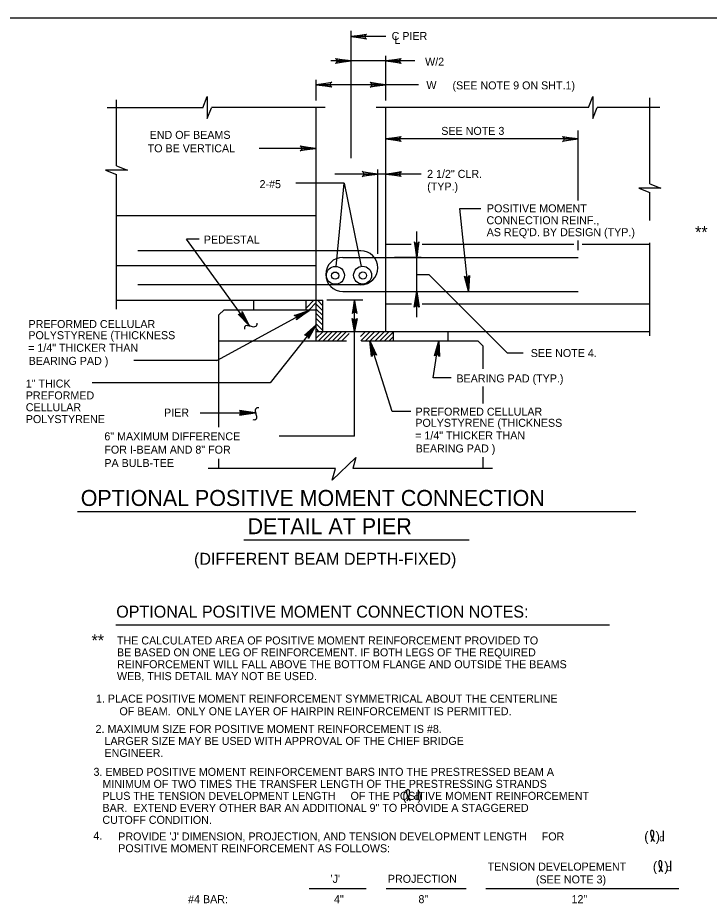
# Model space of a CAD drawing. Extents: x 639980 to 641204, y 298038 to 300414.
# Drawn here: x 640536.4 to 640795.5, y 298284.8 to 298616.8 of the extents above; entities that cross this region are included whole.
import ezdxf

# ---------------------------------------------------------------- set-up
doc = ezdxf.new("R2010")
doc.units = 0
for name, color, linetype in [('1', 7, 'Continuous'), ('2', 7, 'Continuous'), ('3', 7, 'Continuous')]:
    doc.layers.add(name, color=color, linetype=linetype)

msp = doc.modelspace()

# ---------------------------------------------------------------- linework, layer by layer
at = {"layer": '1'}
for p, q in [((640661.25, 298564.12), (640661.25, 298611.8)), ((640648.23, 298495.65), (640648.23, 298583.06)), ((640674.27, 298499.17), (640674.27, 298583.06)), ((640655.64, 298523.56), (640658.65, 298554.73)), ((640644.39, 298507.32), (640644.39, 298510.84)), ((640677.19, 298495.65), (640677.19, 298499.17)), ((640654.23, 298443.37), (640663.07, 298451.9)), ((640663.07, 298451.9), (640661.91, 298447.85)), ((640654.23, 298443.37), (640655.42, 298447.85))]:
    msp.add_line(p, q, dxfattribs=at)
for points in [[(640625.91, 298502.24), (640625.85, 298501.43), (640625.43, 298501), (640624.67, 298500.82), (640623.95, 298501.04), (640623.19, 298501.19), (640622.43, 298501.32), (640621.67, 298501.24), (640621.34, 298500.67), (640621.34, 298500.06)], [(640626.75, 298470.55), (640625.94, 298470.48), (640625.51, 298470.07), (640625.34, 298469.31), (640625.55, 298468.59), (640625.71, 298467.83), (640625.84, 298467.06), (640625.75, 298466.3), (640625.18, 298465.98), (640624.58, 298465.98)]]:
    msp.add_spline(points, degree=3, dxfattribs=at)
at = {"layer": '2'}
for p, q in [((640020.31, 298616.78), (640806.31, 298616.78)), ((640674.27, 298609.72), (640661.25, 298609.72)), ((640674.27, 298585.75), (640674.27, 298602.54)), ((640661.25, 298600.56), (640653.65, 298600.56)), ((640674.27, 298600.56), (640661.25, 298600.56)), ((640685.17, 298600.56), (640674.27, 298600.56)), ((640648.23, 298585.75), (640648.23, 298593.54)), ((640674.27, 298591.66), (640648.23, 298591.66)), ((640686.59, 298591.66), (640674.27, 298591.66)), ((640573.35, 298561.2), (640573.35, 298586)), ((640605.78, 298583), (640607.41, 298587.19)), ((640607.41, 298587.19), (640607.41, 298578.94)), ((640750.26, 298583.11), (640751.89, 298587.3)), ((640751.89, 298587.3), (640751.89, 298579.05)), ((640773.23, 298554.51), (640773.23, 298586.73)), ((640605.78, 298583), (640569.83, 298583)), ((640607.41, 298578.94), (640609, 298583)), ((640651.53, 298583.06), (640609, 298583.06)), ((640750.26, 298583.06), (640670.64, 298583.06)), ((640751.89, 298579.05), (640753.48, 298583.11)), ((640777.01, 298583.11), (640753.48, 298583.11)), ((640746.33, 298548.32), (640746.33, 298574.48)), ((640746.33, 298571.34), (640674.27, 298571.34)), ((640648.04, 298567.77), (640626.88, 298567.77)), ((640577.54, 298559.57), (640569.29, 298559.57)), ((640569.29, 298559.57), (640573.35, 298557.98)), ((640573.35, 298561.2), (640577.54, 298559.57)), ((640671.3, 298528.21), (640671.3, 298559.94)), ((640573.41, 298507.57), (640573.41, 298557.98)), ((640674.27, 298558.15), (640655.13, 298558.15)), ((640687.59, 298558.15), (640674.27, 298558.15)), ((640658.65, 298554.73), (640640.54, 298554.73)), ((640658.65, 298554.73), (640665.01, 298523.57)), ((640777.34, 298552.88), (640769.1, 298552.88)), ((640769.1, 298552.88), (640773.16, 298551.29)), ((640773.16, 298554.51), (640777.34, 298552.88)), ((640773.23, 298540.76), (640773.23, 298551.29)), ((640573.41, 298542.68), (640648.23, 298542.68)), ((640702, 298545.23), (640709.84, 298545.23)), ((640705.32, 298514.23), (640702, 298545.23)), ((640623.1, 298501.38), (640599.61, 298533.81)), ((640604.35, 298533.81), (640599.61, 298533.81)), ((640746.33, 298529.65), (640746.33, 298533.26)), ((640664.9, 298529.44), (640581.38, 298529.44)), ((640674.27, 298531.85), (640683.84, 298531.85)), ((640687.93, 298531.85), (640744.74, 298531.85)), ((640747.81, 298531.85), (640773.23, 298531.85)), ((640773.23, 298497.55), (640773.23, 298532.41)), ((640658.17, 298526.94), (640746.33, 298526.94)), ((640687.59, 298526.94), (640677.54, 298526.94)), ((640573.41, 298523.86), (640648.23, 298523.86)), ((640685.89, 298520.53), (640690.44, 298520.53)), ((640719.91, 298491.09), (640690.44, 298520.53)), ((640664.9, 298516.62), (640581.38, 298516.62)), ((640658.17, 298514.12), (640746.33, 298514.12)), ((640573.41, 298510.84), (640650.7, 298510.84)), ((640624.79, 298507.32), (640624.79, 298510.84)), ((640644.39, 298507.93), (640647.34, 298510.88)), ((640645.52, 298507.29), (640648.23, 298510)), ((640648.68, 298510.84), (640650.7, 298508.82)), ((640650.7, 298499.21), (640650.7, 298510.84)), ((640665.65, 298510.84), (640652.17, 298510.84)), ((640662.58, 298499.17), (640662.58, 298510.75)), ((640674.59, 298509.48), (640683.9, 298509.48)), ((640687.87, 298509.48), (640773.23, 298509.48)), ((640611.77, 298505.37), (640613.69, 298507.29)), ((640613.69, 298507.29), (640648.23, 298507.29)), ((640648.23, 298509.38), (640650.7, 298506.9)), ((640648.23, 298507.58), (640650.7, 298505.11)), ((640610.94, 298488.29), (640641.91, 298505.11)), ((640611.77, 298463.3), (640611.77, 298505.37)), ((640648.23, 298505.93), (640650.7, 298503.46)), ((640648.23, 298503.99), (640650.7, 298501.52)), ((640648.23, 298501.71), (640630.91, 298479.97)), ((640648.23, 298502.04), (640650.7, 298499.57)), ((640648.23, 298500.1), (640649.12, 298499.21)), ((640648.23, 298499.17), (640773.23, 298499.17)), ((640648.23, 298496.62), (640650.78, 298499.17)), ((640649.03, 298495.65), (640652.55, 298499.17)), ((640650.79, 298495.65), (640654.31, 298499.17)), ((640652.56, 298495.65), (640656.08, 298499.17)), ((640654.33, 298495.65), (640657.85, 298499.17)), ((640656.1, 298495.65), (640659.62, 298499.17)), ((640657.86, 298495.65), (640660.61, 298498.4)), ((640662.58, 298459.94), (640662.58, 298499.17)), ((640664.79, 298497.28), (640666.69, 298499.17)), ((640664.93, 298495.65), (640668.46, 298499.17)), ((640666.7, 298495.65), (640670.22, 298499.17)), ((640668.47, 298495.65), (640671.99, 298499.17)), ((640670.24, 298495.65), (640673.76, 298499.17)), ((640672.01, 298495.65), (640675.53, 298499.17)), ((640673.77, 298495.65), (640677.19, 298499.07)), ((640675.54, 298495.65), (640677.19, 298497.3)), ((640697.7, 298495.65), (640697.7, 298499.17)), ((640611.77, 298495.65), (640659.5, 298495.65)), ((640665.14, 298495.65), (640708.77, 298495.65)), ((640676.7, 298469.15), (640668.29, 298495.65)), ((640692.08, 298481.73), (640694.21, 298495.65)), ((640710.73, 298493.7), (640708.77, 298495.65)), ((640710.73, 298485.19), (640710.73, 298493.7)), ((640725.77, 298491.09), (640719.91, 298491.09)), ((640610.94, 298488.29), (640579.86, 298488.29)), ((640630.91, 298479.97), (640564.33, 298479.97)), ((640698.83, 298481.73), (640692.08, 298481.73)), ((640710.73, 298472.16), (640710.73, 298478.51)), ((640604.75, 298468.67), (640625.3, 298468.67)), ((640683.71, 298469.15), (640676.7, 298469.15)), ((640662.58, 298459.94), (640634.35, 298459.94)), ((640611.77, 298447.85), (640611.77, 298451.48)), ((640710.73, 298447.85), (640710.73, 298452.01)), ((640655.42, 298447.85), (640607.71, 298447.85)), ((640714.26, 298447.85), (640661.91, 298447.85)), ((640558.77, 298431.71), (640767.95, 298431.71)), ((640621.05, 298421.12), (640705.53, 298421.12)), ((640573.13, 298389.22), (640758.14, 298389.22)), ((640682.78, 298327.39), (640682.78, 298327.39)), ((640683.19, 298326.87), (640683.11, 298327.07)), ((640686.57, 298323.52), (640686.57, 298327.35)), ((640682.06, 298326.82), (640682.07, 298326.26)), ((640682.08, 298326.15), (640682.24, 298325.45)), ((640682.16, 298323.25), (640682.49, 298323.64)), ((640682.27, 298325.36), (640682.51, 298324.78)), ((640682.54, 298324.72), (640682.92, 298324.03)), ((640682.56, 298323.74), (640682.76, 298324.1)), ((640682.8, 298324.21), (640683.02, 298324.95)), ((640682.95, 298323.98), (640683.46, 298323.25)), ((640683.04, 298325), (640683.21, 298325.88)), ((640683.22, 298325.98), (640683.24, 298326.63)), ((640773.5, 298311.5), (640773.51, 298310.95)), ((640773.52, 298310.83), (640773.68, 298310.14)), ((640774.22, 298312.08), (640774.22, 298312.08)), ((640774.48, 298309.69), (640774.65, 298310.57)), ((640774.63, 298311.56), (640774.55, 298311.76)), ((640774.66, 298310.67), (640774.68, 298311.32)), ((640778.39, 298308.15), (640778.39, 298311.98)), ((640773.6, 298307.94), (640773.93, 298308.33)), ((640773.71, 298310.05), (640773.95, 298309.47)), ((640773.98, 298309.41), (640774.36, 298308.72)), ((640774, 298308.43), (640774.2, 298308.79)), ((640774.24, 298308.9), (640774.46, 298309.64)), ((640774.39, 298308.67), (640774.9, 298307.94)), ((640777.29, 298300.74), (640777.28, 298300.75)), ((640777.69, 298300.22), (640777.61, 298300.42)), ((640781.13, 298296.88), (640781.13, 298300.71)), ((640776.56, 298300.17), (640776.57, 298299.62)), ((640776.58, 298299.5), (640776.74, 298298.81)), ((640776.66, 298296.6), (640776.99, 298296.99)), ((640776.77, 298298.71), (640777.01, 298298.13)), ((640777.04, 298298.07), (640777.42, 298297.39)), ((640777.06, 298297.09), (640777.26, 298297.46)), ((640777.3, 298297.57), (640777.52, 298298.31)), ((640777.45, 298297.34), (640777.96, 298296.6)), ((640777.54, 298298.36), (640777.71, 298299.23)), ((640777.73, 298299.34), (640777.74, 298299.99)), ((640645.61, 298290.38), (640666.89, 298290.38)), ((640674.37, 298290.38), (640704.4, 298290.38)), ((640711.75, 298290.38), (640784.13, 298290.38))]:
    msp.add_line(p, q, dxfattribs=at)
for points in [[(640666.78, 298609.03), (640666.58, 298609.43), (640661.25, 298609.72), (640666.78, 298609.03), (640667.07, 298608.78), (640661.25, 298609.72), (640666.57, 298609.98), (640666.77, 298610.38), (640661.25, 298609.72), (640667.07, 298610.65), (640666.77, 298610.38)], [(640655.71, 298601.26), (640655.92, 298600.86), (640661.25, 298600.56), (640655.71, 298601.26), (640655.43, 298601.5), (640661.25, 298600.56), (640655.92, 298600.3), (640655.73, 298599.9), (640661.25, 298600.56), (640655.43, 298599.64), (640655.73, 298599.9)], [(640679.8, 298599.87), (640679.6, 298600.27), (640674.27, 298600.56), (640679.8, 298599.87), (640680.09, 298599.63), (640674.27, 298600.56), (640679.59, 298600.83), (640679.79, 298601.22), (640674.27, 298600.56), (640680.09, 298601.49), (640679.79, 298601.22)], [(640653.76, 298590.97), (640653.56, 298591.37), (640648.23, 298591.66), (640653.76, 298590.97), (640654.05, 298590.73), (640648.23, 298591.66), (640653.55, 298591.93), (640653.75, 298592.32), (640648.23, 298591.66), (640654.05, 298592.59), (640653.75, 298592.32)], [(640653.76, 298590.97), (640653.56, 298591.37), (640648.23, 298591.66), (640653.76, 298590.97), (640654.05, 298590.73), (640648.23, 298591.66), (640653.55, 298591.93), (640653.75, 298592.32), (640648.23, 298591.66), (640654.05, 298592.59), (640653.75, 298592.32)], [(640668.73, 298592.36), (640668.94, 298591.96), (640674.27, 298591.66), (640668.73, 298592.36), (640668.45, 298592.6), (640674.27, 298591.66), (640668.94, 298591.4), (640668.75, 298591), (640674.27, 298591.66), (640668.45, 298590.74), (640668.75, 298591)], [(640679.8, 298570.65), (640679.6, 298571.05), (640674.27, 298571.34), (640679.8, 298570.65), (640680.09, 298570.41), (640674.27, 298571.34), (640679.59, 298571.61), (640679.79, 298572), (640674.27, 298571.34), (640680.09, 298572.27), (640679.79, 298572)], [(640740.8, 298572.04), (640741, 298571.64), (640746.33, 298571.34), (640740.8, 298572.04), (640740.51, 298572.28), (640746.33, 298571.34), (640741.01, 298571.08), (640740.81, 298570.68), (640746.33, 298571.34), (640740.51, 298570.42), (640740.81, 298570.68)], [(640642.5, 298568.47), (640642.71, 298568.07), (640648.04, 298567.77), (640642.5, 298568.47), (640642.22, 298568.71), (640648.04, 298567.77), (640642.71, 298567.51), (640642.52, 298567.11), (640648.04, 298567.77), (640642.22, 298566.85), (640642.52, 298567.11)], [(640665.77, 298558.84), (640665.98, 298558.44), (640671.3, 298558.15), (640665.77, 298558.84), (640665.49, 298559.09), (640671.3, 298558.15), (640665.98, 298557.89), (640665.79, 298557.49), (640671.3, 298558.15), (640665.49, 298557.22), (640665.79, 298557.49)], [(640679.8, 298557.45), (640679.6, 298557.85), (640674.27, 298558.15), (640679.8, 298557.45), (640680.09, 298557.21), (640674.27, 298558.15), (640679.59, 298558.41), (640679.79, 298558.81), (640674.27, 298558.15), (640680.09, 298559.07), (640679.79, 298558.81)], [(640685.19, 298532.47), (640685.59, 298532.27), (640685.89, 298526.94), (640685.19, 298532.47), (640684.95, 298532.76), (640685.89, 298526.94), (640686.15, 298532.26), (640686.55, 298532.46), (640685.89, 298526.94), (640686.81, 298532.76), (640686.55, 298532.46)], [(640705.42, 298519.81), (640705.05, 298519.56), (640705.32, 298514.23), (640705.42, 298519.81), (640705.64, 298520.11), (640705.32, 298514.23), (640704.49, 298519.49), (640704.08, 298519.65), (640705.32, 298514.23), (640703.78, 298519.92), (640704.08, 298519.65)], [(640685.19, 298508.58), (640685.59, 298508.79), (640685.89, 298514.12), (640685.19, 298508.58), (640684.95, 298508.3), (640685.89, 298514.12), (640686.15, 298508.8), (640686.55, 298508.6), (640685.89, 298514.12), (640686.81, 298508.3), (640686.55, 298508.6)], [(640663.28, 298506.14), (640662.88, 298506.31), (640662.58, 298510.75), (640663.28, 298506.14), (640663.52, 298505.91), (640662.58, 298510.75), (640662.32, 298506.32), (640661.92, 298506.16), (640662.58, 298510.75), (640661.66, 298505.91), (640661.92, 298506.16)], [(640620.47, 298506.3), (640620.26, 298505.9), (640623.1, 298501.38), (640620.47, 298506.3), (640620.5, 298506.67), (640623.1, 298501.38), (640619.81, 298505.57), (640619.37, 298505.5), (640623.1, 298501.38), (640618.98, 298505.59), (640619.37, 298505.5)], [(640640.33, 298505.12), (640640.7, 298504.86), (640645.56, 298507.05), (640640.33, 298505.12), (640639.96, 298505.2), (640645.56, 298507.05), (640640.96, 298504.36), (640640.97, 298503.92), (640645.56, 298507.05), (640640.82, 298503.55), (640640.97, 298503.92)], [(640663.28, 298503.79), (640662.88, 298503.62), (640662.58, 298499.17), (640663.28, 298503.79), (640663.52, 298504.02), (640662.58, 298499.17), (640662.32, 298503.61), (640661.92, 298503.77), (640662.58, 298499.17), (640661.66, 298504.02), (640661.92, 298503.77)], [(640644.24, 298497.81), (640644.68, 298497.72), (640648.23, 298501.71), (640644.24, 298497.81), (640643.87, 298497.74), (640648.23, 298501.71), (640645.12, 298497.38), (640645.31, 298496.98), (640648.23, 298501.71), (640645.33, 298496.58), (640645.31, 298496.98)], [(640669.13, 298490.14), (640669.46, 298490.45), (640668.29, 298495.65), (640669.13, 298490.14), (640668.98, 298489.8), (640668.29, 298495.65), (640670, 298490.6), (640670.43, 298490.52), (640668.29, 298495.65), (640670.77, 298490.31), (640670.43, 298490.52)], [(640692.85, 298490.24), (640693.28, 298490.4), (640694.21, 298495.65), (640692.85, 298490.24), (640692.58, 298489.99), (640694.21, 298495.65), (640693.83, 298490.34), (640694.2, 298490.1), (640694.21, 298495.65), (640694.43, 298489.77), (640694.2, 298490.1)], [(640619.77, 298467.98), (640619.97, 298468.38), (640625.3, 298468.67), (640619.77, 298467.98), (640619.48, 298467.74), (640625.3, 298468.67), (640619.98, 298468.94), (640619.78, 298469.33), (640625.3, 298468.67), (640619.48, 298469.6), (640619.78, 298469.33)], [(640682.38, 298327.4), (640682.33, 298327.39), (640682.17, 298327.18)], [(640773.82, 298312.09), (640773.77, 298312.08), (640773.61, 298311.87)], [(640776.88, 298300.76), (640776.83, 298300.74), (640776.68, 298300.53)]]:
    msp.add_lwpolyline(points, dxfattribs=at)
for centre, radius in [((640655.39, 298520.21), 3.36), ((640665.6, 298520.26), 3.36), ((640655.3, 298520.09), 1.35), ((640665.71, 298520.14), 1.35)]:
    msp.add_circle(centre, radius, dxfattribs=at)
for centre, radius, start, end in [((640664.9, 298523.03), 6.41, 270, 90), ((640658.17, 298520.53), 6.41, 90, 270), ((640682.64, 298326.83), 0.583, 142.942, 181.1567), ((640682.56, 298326.85), 0.583, 68.3745, 108.4443), ((640682.57, 298326.85), 0.583, 22.4358, 68.3745), ((640682.65, 298326.64), 0.583, 358.8549, 22.4358), ((640682.65, 298326.27), 0.583, 181.1567, 192.772), ((640682.81, 298325.58), 0.583, 192.772, 202.4051), ((640682.05, 298324.02), 0.583, 319.6823, 331.4731), ((640683.05, 298325), 0.583, 202.4051, 209.0413), ((640682.24, 298324.38), 0.583, 331.4731, 343.3094), ((640683.43, 298324.32), 0.583, 209.0413, 214.8098), ((640682.46, 298325.12), 0.583, 343.3094, 348.6689), ((640682.64, 298326), 0.583, 348.6689, 358.8549), ((640774.08, 298311.52), 0.583, 142.942, 181.1567), ((640774.09, 298310.96), 0.583, 181.1567, 192.772), ((640774, 298311.54), 0.583, 68.3745, 108.4443), ((640774.01, 298311.53), 0.583, 22.4358, 68.3745), ((640774.09, 298311.33), 0.583, 358.8549, 22.4358), ((640774.08, 298310.68), 0.583, 348.6689, 358.8549), ((640774.25, 298310.27), 0.583, 192.772, 202.4051), ((640773.49, 298308.71), 0.583, 319.6823, 331.4731), ((640774.49, 298309.69), 0.583, 202.4051, 209.0413), ((640773.68, 298309.07), 0.583, 331.4731, 343.3094), ((640774.87, 298309), 0.583, 209.0413, 214.8098), ((640773.9, 298309.81), 0.583, 343.3094, 348.6689), ((640777.14, 298300.18), 0.583, 142.942, 181.1567), ((640777.06, 298300.2), 0.583, 68.3745, 108.4443), ((640777.07, 298300.2), 0.583, 22.4358, 68.3745), ((640777.15, 298299.63), 0.583, 181.1567, 192.772), ((640777.31, 298298.94), 0.583, 192.772, 202.4051), ((640776.55, 298297.37), 0.583, 319.6823, 331.4731), ((640777.55, 298298.35), 0.583, 202.4051, 209.0413), ((640776.74, 298297.73), 0.583, 331.4731, 343.3094), ((640777.93, 298297.67), 0.583, 209.0413, 214.8098), ((640776.97, 298298.47), 0.583, 343.3094, 348.6689), ((640777.15, 298300), 0.583, 358.8549, 22.4358), ((640777.14, 298299.35), 0.583, 348.6689, 358.8549)]:
    msp.add_arc(centre, radius, start, end, dxfattribs=at)
at = {"layer": '3'}
msp.add_line((640685.89, 298504.5), (640685.89, 298536.62), dxfattribs=at)

# ---------------------------------------------------------------- texts
at = {"layer": '1'}
for s, height, p in [("PROVIDE 'J' DIMENSION, PROJECTION, AND TENSION DEVELOPMENT LENGTH     FOR ", 2.9999, (640574.03, 298308.38)), ('POSITIVE MOMENT REINFORCEMENT AS FOLLOWS:', 2.9999, (640574.03, 298303.94)), ('TENSION DEVELOPEMENT', 2.9999, (640712.43, 298297.07)), ("'J'", 3, (640653.59, 298292.49)), ('PROJECTION', 3, (640675.06, 298292.49)), ('(SEE NOTE 3)', 2.9999, (640730.52, 298292.27)), ('     #4 BAR:', 2.9999, (640594.64, 298284.86)), ('4"', 3, (640654.87, 298284.86)), ('8"', 3, (640686.51, 298284.86)), ('12"', 3, (640743.87, 298284.86))]:
    msp.add_text(s, height=height, dxfattribs=at).set_placement(p)
at = {"layer": '2'}
for s, height, p in [('(SEE NOTE 9 ON SHT.1)', 3, (640699.27, 298589.91)), ('SEE NOTE 3', 3, (640695.07, 298572.85)), ('SEE NOTE 4.', 3, (640728.59, 298489.58)), ('OPTIONAL POSITIVE MOMENT CONNECTION', 6, (640559.99, 298433.76)), ('DETAIL AT PIER', 6, (640622.49, 298423.18)), ('(DIFFERENT BEAM DEPTH-FIXED)', 4.5, (640602.43, 298411.69)), ('OPTIONAL POSITIVE MOMENT CONNECTION NOTES:', 4.5, (640573.29, 298391.89)), ('THE CALCULATED AREA OF POSITIVE MOMENT REINFORCEMENT PROVIDED TO ', 3, (640573.56, 298381.84)), ('BE BASED ON ONE LEG OF REINFORCEMENT. IF BOTH LEGS OF THE REQUIRED', 3, (640573.56, 298377.38)), ('REINFORCEMENT WILL FALL ABOVE THE BOTTOM FLANGE AND OUTSIDE THE BEAMS', 3, (640573.56, 298372.93)), ('WEB, THIS DETAIL MAY NOT BE USED.', 3, (640573.56, 298368.47)), ('1. PLACE POSITIVE MOMENT REINFORCEMENT SYMMETRICAL ABOUT THE CENTERLINE', 3, (640565.68, 298360.04)), ('OF BEAM.  ONLY ONE LAYER OF HAIRPIN REINFORCEMENT IS PERMITTED.', 3, (640574.49, 298355.3)), ('2. MAXIMUM SIZE FOR POSITIVE MOMENT REINFORCEMENT IS #8.', 3, (640565.54, 298348.68)), ('   LARGER SIZE MAY BE USED WITH APPROVAL OF THE CHIEF BRIDGE', 3, (640565.54, 298344.18)), ('   ENGINEER.', 3, (640565.54, 298339.68)), ('3. EMBED POSITIVE MOMENT REINFORCEMENT BARS INTO THE PRESTRESSED BEAM A', 3, (640564.77, 298332.59)), ('   MINIMUM OF TWO TIMES THE TRANSFER LENGTH OF THE PRESTRESSING STRANDS', 3, (640564.77, 298328.09)), ('(   )', 3.6, (640680.51, 298323.45)), ('   PLUS THE TENSION DEVELOPMENT LENGTH     OF THE POSITIVE MOMENT REINFORCEMENT', 3, (640564.77, 298323.59)), ('d', 2.5, (640684.91, 298323.52)), ('   BAR.  EXTEND EVERY OTHER BAR AN ADDITIONAL 9" TO PROVIDE A STAGGERED', 3, (640564.77, 298319.09)), ('   CUTOFF CONDITION.', 3, (640564.77, 298314.59)), ('(  )', 3.6, (640771.11, 298308.07)), ('d', 2.5, (640776.73, 298308.08)), ('(  )', 3.6, (640774.34, 298296.83)), ('d', 2.5, (640779.47, 298296.88))]:
    msp.add_text(s, height=height, dxfattribs=at).set_placement(p)
at = {"layer": '3'}
for s, height, p in [('C PIER', 2.999, (640676.46, 298608.42)), ('L', 3, (640677.49, 298606.96)), ('W/2', 2.997, (640689.01, 298598.81)), ('W', 3, (640689.5, 298590)), ('END OF BEAMS', 2.9989, (640585.8, 298571.36)), ('TO BE VERTICAL', 2.9989, (640585.06, 298566.33)), ('2 1/2" CLR.', 2.9968, (640689.77, 298556.74)), ('2-#5', 2.997, (640626.99, 298552.9)), ('(TYP.)', 2.997, (640689.79, 298552.01)), ('POSITIVE MOMENT', 2.9968, (640712.18, 298543.83)), ('CONNECTION REINF.,', 2.9968, (640712.01, 298539.36)), ("AS REQ'D. BY DESIGN (TYP.)", 2.9968, (640712.09, 298534.89)), ('**', 4.495, (640790.17, 298534.15)), ('PEDESTAL', 2.999, (640606.11, 298532.1)), ('PREFORMED CELLULAR', 2.9989, (640540.43, 298500.45)), ('POLYSTYRENE (THICKNESS ', 2.9989, (640540.36, 298496.27)), ('= 1/4" THICKER THAN', 2.9989, (640540.29, 298491.54)), ('BEARING PAD )', 2.9989, (640540.47, 298486.64)), ('BEARING PAD (TYP.)', 2.9989, (640700.75, 298480.06)), ('1" THICK', 2.999, (640539.4, 298478.14)), ('PREFORMED', 2.999, (640539.4, 298473.7)), ('CELLULAR', 2.999, (640539.4, 298469.26)), ('PIER', 2.999, (640591.2, 298467.26)), ('PREFORMED CELLULAR', 2.9989, (640685.42, 298467.6)), ('POLYSTYRENE', 2.9989, (640539.4, 298464.82)), ('POLYSTYRENE (THICKNESS ', 2.9989, (640685.35, 298463.42)), ('6" MAXIMUM DIFFERENCE', 2.9999, (640568.84, 298458.37)), ('= 1/4" THICKER THAN', 2.9989, (640685.28, 298458.69)), ('FOR I-BEAM AND 8" FOR', 2.9999, (640568.84, 298453.37)), ('BEARING PAD )', 2.9989, (640685.46, 298453.8)), ('PA BULB-TEE', 2.9999, (640568.84, 298448.37)), ('**', 4.495, (640564.04, 298381.11)), ('4.', 2.997, (640564.7, 298308.65))]:
    msp.add_text(s, height=height, dxfattribs=at).set_placement(p)

doc.saveas('drawing.dxf')
